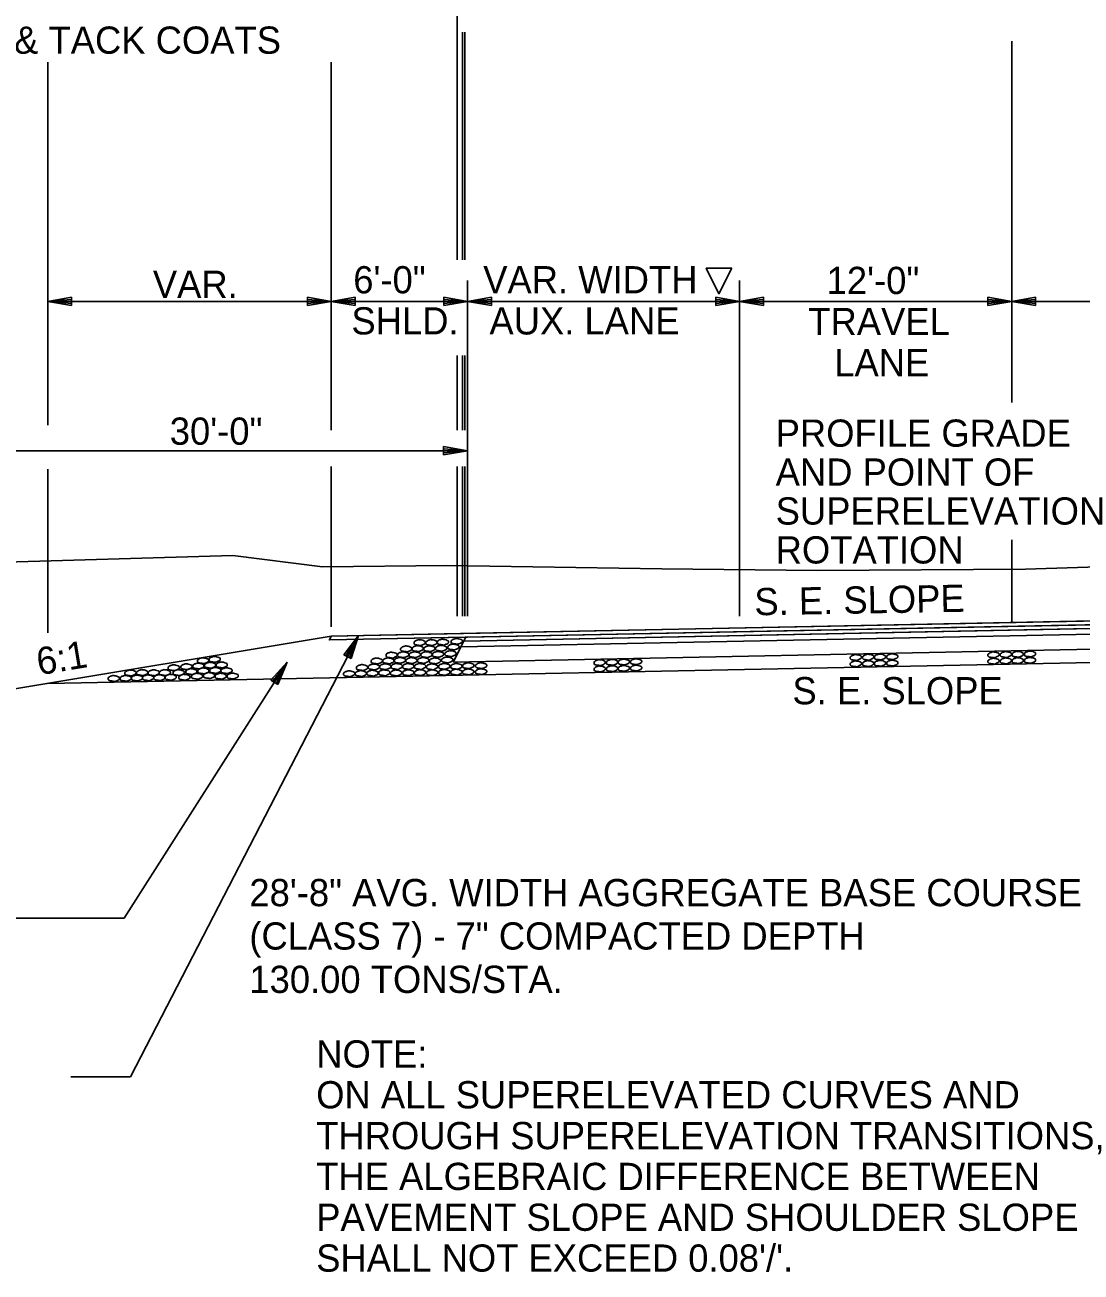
# Model space of a CAD drawing. Extents: x 1734743 to 1735935, y 759845 to 763831.
# Drawn here: x 1735665.4 to 1735712, y 762835.7 to 762890.6 of the extents above; entities that cross this region are included whole.
import ezdxf

# ---------------------------------------------------------------- set-up
doc = ezdxf.new("R2010")
doc.units = 0
for name, color, linetype in [('1', 7, 'Continuous'), ('10', 7, 'Continuous'), ('19', 7, 'Continuous'), ('9', 7, 'Continuous'), ('Level 1', 7, 'Continuous'), ('R_Prop Surface', 7, 'Continuous')]:
    doc.layers.add(name, color=color, linetype=linetype)

# ---------------------------------------------------------------- blocks, each defined once
blk = doc.blocks.new('ROCKS')
at = {"layer": '1'}
blk.add_spline([(0.013, 0.06), (0.053, 0.053), (0.107, 0.033), (0.133, 0.013), (0.133, -0.007), (0.12, -0.033), (0.107, -0.04), (0.073, -0.053), (0.033, -0.067), (0.013, -0.067), (-0.02, -0.06), (-0.06, -0.053), (-0.087, -0.047), (-0.113, -0.02), (-0.113, -0.007), (-0.107, 0.02), (-0.087, 0.033), (-0.067, 0.047), (-0.033, 0.053), (-0.02, 0.06), (0.013, 0.06)], degree=3, dxfattribs=at)

msp = doc.modelspace()

# ---------------------------------------------------------------- linework, layer by layer
at = {"layer": '10'}
msp.add_lwpolyline([(1735696.619, 762879.923), (1735696.057, 762878.798), (1735695.494, 762879.923)], close=True, dxfattribs=at)
at = {"layer": '19'}
for p, q in [((1735684.517, 762880.288), (1735684.517, 762891.579)), ((1735684.746, 762880.288), (1735684.746, 762890.329)), ((1735684.85, 762880.288), (1735684.85, 762890.328)), ((1735708.969, 762874.003), (1735708.969, 762889.935)), ((1735666.455, 762872.998), (1735666.455, 762889.007)), ((1735678.959, 762872.785), (1735678.959, 762889.007)), ((1735684.969, 762864.588), (1735684.969, 762879.376)), ((1735696.969, 762864.588), (1735696.969, 762879.376)), ((1735667.505, 762878.645), (1735666.455, 762878.462)), ((1735666.455, 762878.462), (1735667.505, 762878.278)), ((1735667.505, 762878.549), (1735666.735, 762878.488)), ((1735666.735, 762878.435), (1735667.505, 762878.365)), ((1735667.505, 762878.278), (1735667.505, 762878.645)), ((1735677.909, 762878.645), (1735677.909, 762878.277)), ((1735678.959, 762878.461), (1735677.909, 762878.645)), ((1735678.679, 762878.487), (1735677.909, 762878.549)), ((1735677.909, 762878.277), (1735678.959, 762878.461)), ((1735677.909, 762878.365), (1735678.679, 762878.435)), ((1735680.009, 762878.645), (1735678.959, 762878.461)), ((1735678.959, 762878.461), (1735680.009, 762878.277)), ((1735678.969, 762878.461), (1735684.969, 762878.461)), ((1735680.009, 762878.548), (1735679.239, 762878.487)), ((1735679.239, 762878.435), (1735680.009, 762878.365)), ((1735680.009, 762878.277), (1735680.009, 762878.645)), ((1735683.919, 762878.645), (1735683.919, 762878.277)), ((1735684.969, 762878.461), (1735683.919, 762878.645)), ((1735684.689, 762878.487), (1735683.919, 762878.549)), ((1735683.919, 762878.277), (1735684.969, 762878.461)), ((1735683.919, 762878.365), (1735684.689, 762878.435)), ((1735686.019, 762878.645), (1735684.969, 762878.461)), ((1735696.969, 762878.461), (1735684.969, 762878.461)), ((1735684.969, 762878.461), (1735686.019, 762878.277)), ((1735686.019, 762878.548), (1735685.249, 762878.487)), ((1735685.249, 762878.435), (1735686.019, 762878.365)), ((1735686.019, 762878.277), (1735686.019, 762878.645)), ((1735695.919, 762878.645), (1735695.919, 762878.277)), ((1735696.969, 762878.461), (1735695.919, 762878.645)), ((1735696.689, 762878.487), (1735695.919, 762878.549)), ((1735695.919, 762878.277), (1735696.969, 762878.461)), ((1735695.919, 762878.365), (1735696.689, 762878.435)), ((1735698.019, 762878.645), (1735696.969, 762878.461)), ((1735696.969, 762878.461), (1735708.969, 762878.461)), ((1735696.969, 762878.461), (1735698.019, 762878.277)), ((1735698.019, 762878.548), (1735697.249, 762878.487)), ((1735697.249, 762878.435), (1735698.019, 762878.365)), ((1735698.019, 762878.277), (1735698.019, 762878.645)), ((1735707.919, 762878.645), (1735707.919, 762878.277)), ((1735708.969, 762878.461), (1735707.919, 762878.645)), ((1735708.689, 762878.487), (1735707.919, 762878.549)), ((1735707.919, 762878.277), (1735708.969, 762878.461)), ((1735707.919, 762878.365), (1735708.689, 762878.435)), ((1735710.019, 762878.645), (1735708.969, 762878.461)), ((1735708.969, 762878.461), (1735720.967, 762878.461)), ((1735708.969, 762878.461), (1735710.019, 762878.277)), ((1735710.019, 762878.548), (1735709.249, 762878.487)), ((1735709.249, 762878.435), (1735710.019, 762878.365)), ((1735710.019, 762878.277), (1735710.019, 762878.645)), ((1735684.517, 762872.785), (1735684.517, 762876.08)), ((1735684.746, 762872.785), (1735684.746, 762876.08)), ((1735684.85, 762872.785), (1735684.85, 762876.08)), ((1735655.231, 762871.878), (1735684.959, 762871.878)), ((1735683.909, 762872.061), (1735683.909, 762871.694)), ((1735684.959, 762871.878), (1735683.909, 762872.061)), ((1735684.679, 762871.904), (1735683.909, 762871.965)), ((1735683.909, 762871.694), (1735684.959, 762871.878)), ((1735683.909, 762871.781), (1735684.679, 762871.851)), ((1735678.959, 762864.107), (1735678.959, 762871.185)), ((1735684.517, 762864.588), (1735684.517, 762871.185)), ((1735684.746, 762864.588), (1735684.746, 762871.185)), ((1735684.85, 762864.588), (1735684.85, 762871.185)), ((1735666.455, 762863.841), (1735666.455, 762871.065)), ((1735708.969, 762864.303), (1735708.969, 762867.944)), ((1735726.962, 762864.663), (1735678.956, 762863.703)), ((1735725.06, 762864.458), (1735678.872, 762863.534)), ((1735721.141, 762864.213), (1735684.801, 762863.486)), ((1735721.141, 762864.213), (1735684.801, 762863.486)), ((1735678.956, 762863.703), (1735655.228, 762859.748)), ((1735680.161, 762863.727), (1735679.517, 762862.877)), ((1735680.014, 762863.489), (1735679.602, 762862.84)), ((1735679.842, 762862.712), (1735680.161, 762863.727)), ((1735721.265, 762863.965), (1735684.674, 762863.233)), ((1735684.674, 762863.233), (1735721.265, 762863.965)), ((1735721.265, 762863.965), (1735684.674, 762863.233)), ((1735684.801, 762863.486), (1735684.674, 762863.233)), ((1735679.766, 762862.753), (1735680.058, 762863.466)), ((1735721.595, 762863.305), (1735684.338, 762862.56)), ((1735684.338, 762862.56), (1735721.595, 762863.305)), ((1735684.674, 762863.233), (1735684.338, 762862.56)), ((1735720.976, 762862.71), (1735666.455, 762861.619)), ((1735669.821, 762851.27), (1735677.011, 762862.551)), ((1735677.011, 762862.551), (1735676.292, 762861.763)), ((1735676.602, 762861.569), (1735677.011, 762862.551)), ((1735679.517, 762862.877), (1735679.842, 762862.712)), ((1735676.844, 762862.327), (1735676.374, 762861.718)), ((1735676.529, 762861.617), (1735676.885, 762862.3)), ((1735676.292, 762861.763), (1735676.602, 762861.569)), ((1735659.945, 762851.27), (1735669.821, 762851.27))]:
    msp.add_line(p, q, dxfattribs=at)
for points in [[(1735613.494, 762866.591), (1735663.071, 762866.914), (1735674.619, 762867.254), (1735678.573, 762866.752), (1735684.054, 762866.812), (1735693.534, 762866.668), (1735700.381, 762866.602), (1735709.582, 762866.651), (1735716.449, 762866.88)], [(1735725.06, 762864.458), (1735721.058, 762864.378), (1735684.885, 762863.654), (1735684.885, 762863.654), (1735684.885, 762863.654), (1735678.872, 762863.534), (1735678.956, 762863.703), (1735678.956, 762863.703), (1735685.363, 762863.831), (1735721.057, 762864.545), (1735724.965, 762864.623), (1735724.965, 762864.623), (1735725.06, 762864.458), (1735725.06, 762864.458), (1735725.06, 762864.458)], [(1735721.141, 762864.213), (1735684.801, 762863.486), (1735684.801, 762863.486), (1735684.885, 762863.654), (1735684.885, 762863.654), (1735684.972, 762863.656), (1735721.058, 762864.378), (1735721.058, 762864.378), (1735721.058, 762864.378), (1735721.141, 762864.213), (1735721.141, 762864.213), (1735721.141, 762864.213)]]:
    msp.add_lwpolyline(points, dxfattribs=at)
at = {"layer": '9'}
for p, q in [((1735666.455, 762878.462), (1735678.959, 762878.461)), ((1735680.161, 762863.727), (1735670.107, 762844.268)), ((1735670.107, 762844.268), (1735667.469, 762844.268))]:
    msp.add_line(p, q, dxfattribs=at)
at = {"layer": 'R_Prop Surface'}
for p, q in [((1735678.956, 762863.703), (1735678.872, 762863.534)), ((1735684.885, 762863.654), (1735684.338, 762862.56))]:
    msp.add_line(p, q, dxfattribs=at)

# ---------------------------------------------------------------- block references
at = {"layer": 'Level 1', "xscale": 2.011654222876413}
for p, yscale, rotation in [((1735682.833, 762863.425), 2.0116542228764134, 2.041282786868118), ((1735683.352, 762863.425), 2.0116542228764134, 2.041282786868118), ((1735683.861, 762863.443), 2.0116542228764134, 2.041282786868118), ((1735684.472, 762863.479), 2.0116542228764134, 2.041282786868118), ((1735681.599, 762862.871), 2.0116542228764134, 2.041282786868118), ((1735682.111, 762862.888), 2.0116542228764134, 2.041282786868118), ((1735682.242, 762863.147), 2.0116542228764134, 2.041282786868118), ((1735682.62, 762862.891), 2.0116542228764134, 2.041282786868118), ((1735682.747, 762863.158), 2.0116542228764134, 2.041282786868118), ((1735683.138, 762862.893), 2.0116542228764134, 2.041282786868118), ((1735683.265, 762863.156), 2.0116542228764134, 2.041282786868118), ((1735683.645, 762862.903), 2.0116542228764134, 2.041282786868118), ((1735683.783, 762863.175), 2.0116542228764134, 2.041282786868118), ((1735684.196, 762862.938), 2.0116542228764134, 2.041282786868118), ((1735684.325, 762863.23), 2.0116542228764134, 2.041282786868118), ((1735703.135, 762862.79), 2.0116542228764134, 3.0987721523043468), ((1735703.678, 762862.802), 2.0116542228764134, 3.0987721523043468), ((1735708.145, 762862.885), 2.0116542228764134, 3.0987721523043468), ((1735708.689, 762862.897), 2.0116542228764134, 3.0987721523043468), ((1735709.21, 762862.909), 2.0116542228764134, 3.0987721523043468), ((1735709.753, 762862.921), 2.0116542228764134, 3.0987721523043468), ((1735671.989, 762862.315), 2.011654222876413, 1.8263814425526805), ((1735672.547, 762862.359), 2.011654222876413, 1.8263814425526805), ((1735673.075, 762862.391), 2.011654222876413, 1.8263814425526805), ((1735673.284, 762862.627), 2.011654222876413, 1.8263814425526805), ((1735673.592, 762862.426), 2.011654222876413, 1.8263814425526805), ((1735673.792, 762862.683), 2.011654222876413, 1.8263814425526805), ((1735674.103, 762862.438), 2.011654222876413, 1.8263814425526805), ((1735680.297, 762862.325), 2.0116542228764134, 2.041282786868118), ((1735680.813, 762862.351), 2.0116542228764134, 2.041282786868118), ((1735680.943, 762862.614), 2.0116542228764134, 2.041282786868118), ((1735681.317, 762862.361), 2.0116542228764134, 2.041282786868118), ((1735681.456, 762862.62), 2.0116542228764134, 2.041282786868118), ((1735681.823, 762862.371), 2.0116542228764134, 2.041282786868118), ((1735681.965, 762862.638), 2.0116542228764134, 2.041282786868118), ((1735682.333, 762862.372), 2.0116542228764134, 2.041282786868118), ((1735682.474, 762862.632), 2.0116542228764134, 2.041282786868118), ((1735682.853, 762862.371), 2.0116542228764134, 2.041282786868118), ((1735682.992, 762862.637), 2.0116542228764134, 2.041282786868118), ((1735683.386, 762862.356), 2.0116542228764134, 2.041282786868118), ((1735683.508, 762862.619), 2.0116542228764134, 2.041282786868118), ((1735683.92, 762862.375), 2.0116542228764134, 2.041282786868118), ((1735684.049, 762862.66), 2.0116542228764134, 2.041282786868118), ((1735684.456, 762862.377), 2.0116542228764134, 2.041282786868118), ((1735684.979, 762862.403), 2.0116542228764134, 2.041282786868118), ((1735685.55, 762862.408), 2.0116542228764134, 2.041282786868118), ((1735690.776, 762862.543), 2.0116542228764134, 3.0987721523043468), ((1735690.777, 762862.263), 2.0116542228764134, 3.0987721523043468), ((1735691.319, 762862.555), 2.0116542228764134, 3.0987721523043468), ((1735691.32, 762862.275), 2.0116542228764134, 3.0987721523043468), ((1735691.841, 762862.567), 2.0116542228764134, 3.0987721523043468), ((1735691.842, 762862.287), 2.0116542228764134, 3.0987721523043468), ((1735692.383, 762862.579), 2.0116542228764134, 3.0987721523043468), ((1735692.384, 762862.299), 2.0116542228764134, 3.0987721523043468), ((1735702.07, 762862.767), 2.0116542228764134, 3.0987721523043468), ((1735702.071, 762862.487), 2.0116542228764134, 3.0987721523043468), ((1735702.614, 762862.779), 2.0116542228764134, 3.0987721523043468), ((1735702.615, 762862.499), 2.0116542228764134, 3.0987721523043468), ((1735703.136, 762862.51), 2.0116542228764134, 3.0987721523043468), ((1735703.679, 762862.522), 2.0116542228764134, 3.0987721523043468), ((1735708.146, 762862.605), 2.0116542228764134, 3.0987721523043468), ((1735708.69, 762862.617), 2.0116542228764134, 3.0987721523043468), ((1735709.211, 762862.629), 2.0116542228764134, 3.0987721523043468), ((1735709.754, 762862.641), 2.0116542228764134, 3.0987721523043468), ((1735669.346, 762861.841), 2.011654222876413, 1.8263814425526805), ((1735669.868, 762861.847), 2.011654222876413, 1.8263814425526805), ((1735670.079, 762862.086), 2.011654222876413, 1.8263814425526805), ((1735670.368, 762861.861), 2.011654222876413, 1.8263814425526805), ((1735670.599, 762862.101), 2.011654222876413, 1.8263814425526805), ((1735670.863, 762861.872), 2.011654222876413, 1.8263814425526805), ((1735671.106, 762862.094), 2.011654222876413, 1.8263814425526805), ((1735671.36, 762861.879), 2.011654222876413, 1.8263814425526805), ((1735671.599, 762862.1), 2.011654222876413, 1.8263814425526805), ((1735671.85, 762861.895), 2.011654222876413, 1.8263814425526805), ((1735672.207, 762862.1), 2.011654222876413, 1.8263814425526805), ((1735672.458, 762861.895), 2.011654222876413, 1.8263814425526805), ((1735672.764, 762862.144), 2.011654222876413, 1.8263814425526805), ((1735673.016, 762861.939), 2.011654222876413, 1.8263814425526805), ((1735673.292, 762862.177), 2.011654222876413, 1.8263814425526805), ((1735673.544, 762861.972), 2.011654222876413, 1.8263814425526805), ((1735673.822, 762862.196), 2.011654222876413, 1.8263814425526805), ((1735674.058, 762861.942), 2.011654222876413, 1.8263814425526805), ((1735674.319, 762862.185), 2.011654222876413, 1.8263814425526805), ((1735674.586, 762861.948), 2.011654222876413, 1.8263814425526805), ((1735679.728, 762862.049), 2.0116542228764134, 2.041282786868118), ((1735680.241, 762862.061), 2.0116542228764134, 2.041282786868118), ((1735680.758, 762862.076), 2.0116542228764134, 2.041282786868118), ((1735681.277, 762862.092), 2.0116542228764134, 2.041282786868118), ((1735681.795, 762862.088), 2.0116542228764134, 2.041282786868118), ((1735682.333, 762862.095), 2.0116542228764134, 2.041282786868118), ((1735682.854, 762862.1), 2.0116542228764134, 2.041282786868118), ((1735683.387, 762862.095), 2.0116542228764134, 2.041282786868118), ((1735683.921, 762862.11), 2.0116542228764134, 2.041282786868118), ((1735684.457, 762862.121), 2.0116542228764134, 2.041282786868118), ((1735684.975, 762862.133), 2.0116542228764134, 2.041282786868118), ((1735685.545, 762862.143), 2.0116542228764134, 2.041282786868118)]:
    msp.add_blockref('ROCKS', p, dxfattribs=dict(at, yscale=yscale, rotation=rotation))

# ---------------------------------------------------------------- texts
at = {"layer": '10'}
for s, p in [('VAR.', (1735671.089, 762878.615)), ('PROFILE GRADE', (1735698.556, 762872.053)), ('AND POINT OF', (1735698.556, 762870.337)), ('SUPERELEVATION', (1735698.556, 762868.621)), ('ROTATION  ', (1735698.556, 762866.905)), ('S. E. SLOPE', (1735699.297, 762860.697)), ('NOTE:', (1735678.293, 762844.684)), ('ON ALL SUPERELEVATED CURVES AND', (1735678.293, 762842.884)), ('THROUGH SUPERELEVATION TRANSITIONS,', (1735678.293, 762841.084)), ('THE ALGEBRAIC DIFFERENCE BETWEEN', (1735678.293, 762839.284)), ('PAVEMENT SLOPE AND SHOULDER SLOPE', (1735678.293, 762837.484)), ("SHALL NOT EXCEED 0.08'/'.", (1735678.293, 762835.684))]:
    msp.add_text(s, height=1.2, dxfattribs=at).set_placement(p)
msp.add_text('S. E. SLOPE', height=1.2, rotation=0.9769, dxfattribs=at).set_placement((1735697.628, 762864.619))
at = {"layer": '19'}
for s, p in [('(880 LBS./SQ.YD.) & TACK COATS', (1735650.968, 762889.379)), ('6\'-0"', (1735679.927, 762878.815)), ('VAR. WIDTH ', (1735685.659, 762878.815)), ('12\'-0"', (1735700.805, 762878.785)), ('SHLD.', (1735679.846, 762877.003)), ('AUX. LANE', (1735685.933, 762877.002)), ('TRAVEL', (1735699.997, 762876.973)), ('LANE', (1735701.141, 762875.16)), ('30\'-0"', (1735671.834, 762872.141)), ('28\'-8" AVG. WIDTH AGGREGATE BASE COURSE', (1735675.344, 762851.796)), ('(CLASS 7) - 7" COMPACTED DEPTH', (1735675.344, 762849.884)), ('130.00 TONS/STA.', (1735675.344, 762847.972))]:
    msp.add_text(s, height=1.2, dxfattribs=at).set_placement(p)
msp.add_text('6:1', height=1.2, rotation=9.4511, dxfattribs=at).set_placement((1735666.064, 762861.976))

doc.saveas('drawing.dxf')
